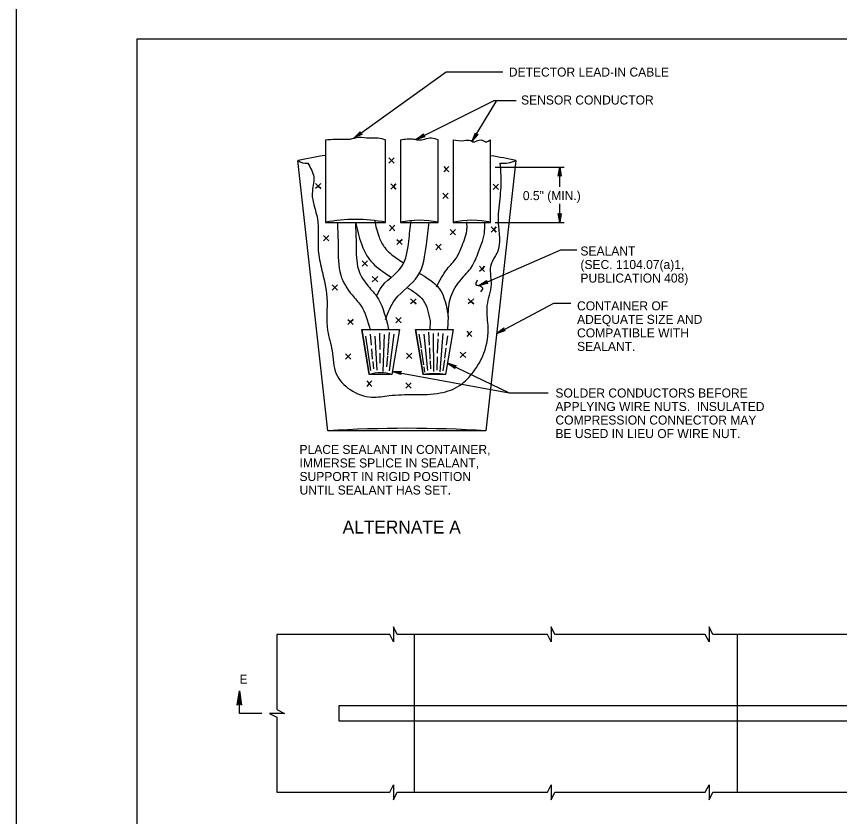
# Model space of a CAD drawing. Extents: x 2709 to 3899, y 22 to 1210.
# Drawn here: x 2708.9 to 2982.7, y 342.4 to 608.7 of the extents above; entities that cross this region are included whole.
import ezdxf

# ---------------------------------------------------------------- set-up
doc = ezdxf.new("R2010")
doc.units = 0
for name, color, linetype in [('1', 7, 'Continuous'), ('2', 7, 'Continuous'), ('3', 7, 'Continuous'), ('PLT-BNDY', 7, 'Continuous')]:
    doc.layers.add(name, color=color, linetype=linetype)

# ---------------------------------------------------------------- blocks, each defined once
blk = doc.blocks.new('RARROW')
at = {"layer": '3'}
blk.add_lwpolyline([(-2.2695, 0.285), (-2.184875, 0.12075), (0, 0), (-2.2695, 0.285), (-2.38575, 0.384625), (0, 0), (-2.183125, -0.108), (-2.262875, -0.2705), (0, 0), (-2.38575, -0.379125), (-2.262875, -0.2705)], dxfattribs=at)

msp = doc.modelspace()

# ---------------------------------------------------------------- linework, layer by layer
at = {"layer": '1'}
for q in [(3534.86, 601.17), (2748.86, 37.17)]:
    msp.add_line((2748.86, 601.17), q, dxfattribs=at)
at = {"layer": '2'}
for p, q in [((2821.13, 568.12), (2851.88, 590.22)), ((2851.88, 590.22), (2870.7, 590.22)), ((2841.88, 567.75), (2867.75, 580.75)), ((2860.5, 567.12), (2868.63, 580.75)), ((2867.75, 580.75), (2875.13, 580.75)), ((2811.63, 562.37), (2811.63, 562.37)), ((2866.63, 562.25), (2866.63, 562.25)), ((2868.13, 558.5), (2891.13, 558.5)), ((2889.63, 552), (2889.63, 558.5)), ((2889.63, 540.12), (2889.63, 546.37)), ((2828, 540.75), (2828, 540.75)), ((2858.75, 539.37), (2858.75, 540.37)), ((2868.13, 540.12), (2891.13, 540.12)), ((2862.75, 519.12), (2890, 531)), ((2890, 531), (2895.25, 531)), ((2842.63, 523.37), (2842.63, 523.37)), ((2838.75, 518.5), (2838.75, 518.5)), ((2848.63, 518.75), (2848.63, 518.75)), ((2868.63, 503.12), (2887.63, 513.25)), ((2887.63, 513.25), (2893.25, 513.25)), ((2846.5, 507.37), (2846.38, 504.5)), ((2852.5, 508.87), (2852.25, 504.5)), ((2823.75, 504.5), (2826.25, 489.5)), ((2832.25, 506.25), (2832.63, 504.5)), ((2836.25, 504.5), (2833.75, 489.5)), ((2841.63, 504.5), (2844.13, 489.5)), ((2854.13, 504.5), (2851.63, 489.5)), ((2825, 502.25), (2826.63, 490.87)), ((2826.5, 503), (2826.88, 499.25)), ((2828.13, 502.25), (2828.75, 491)), ((2829.63, 503.25), (2829.75, 497.87)), ((2831.25, 502.87), (2830.75, 490.5)), ((2832.88, 503.5), (2832.63, 500.75)), ((2834.38, 503), (2832.88, 490.75)), ((2842.75, 503), (2843.5, 498.37)), ((2844.38, 503), (2845.63, 490.87)), ((2846, 503.62), (2846.13, 499.25)), ((2847.5, 503.12), (2847.63, 490.5)), ((2849, 501.37), (2848.88, 496.62)), ((2849.13, 503.37), (2849.13, 502.25)), ((2850.75, 503.12), (2849.75, 490.37)), ((2852.25, 502.37), (2851.88, 499.25)), ((2832.63, 500.5), (2832.25, 496.12)), ((2827, 498.12), (2827.25, 494.62)), ((2829.75, 496.62), (2829.75, 493.25)), ((2832.25, 495.75), (2832, 492.12)), ((2843.5, 497.87), (2844.25, 492.75)), ((2846.25, 498.37), (2846.38, 494.62)), ((2851.75, 498.25), (2851.25, 495)), ((2827.38, 493.87), (2827.63, 491.37)), ((2846.5, 494.12), (2846.63, 491.37)), ((2848.88, 495.37), (2848.75, 491)), ((2851.25, 494.37), (2850.75, 490.75)), ((2852.25, 493.25), (2872.8, 483.37)), ((2833.93, 490.57), (2872.8, 483.37)), ((2844.38, 492.12), (2844.63, 490.25)), ((2872.8, 483.37), (2885.81, 483.37)), ((2841.15, 403.01), (2841.15, 350.51)), ((2948.65, 403.01), (2948.65, 350.51))]:
    msp.add_line(p, q, dxfattribs=at)
for points in [[(2811.63, 567.62), (2811.63, 540.12), (2831.63, 540.12), (2831.63, 567.62)], [(2836.63, 567.62), (2836.63, 540.12), (2849.13, 540.12), (2849.13, 567.62)], [(2854.13, 567.62), (2854.13, 540.12), (2866.63, 540.12), (2866.63, 567.62)], [(2832.75, 561.62), (2833.63, 560.75), (2834.5, 559.87), (2833.63, 560.75), (2834.5, 561.62), (2833.63, 560.75), (2832.75, 559.87)], [(2875, 560.75), (2865, 470.75), (2812.5, 470.75), (2802.5, 560.75)], [(2851, 558.75), (2851.88, 557.87), (2852.75, 557), (2851.88, 557.87), (2852.75, 558.75), (2851.88, 557.87), (2851, 557)], [(2808.38, 553.12), (2809.25, 552.25), (2810.13, 551.37), (2809.25, 552.25), (2810.13, 553.12), (2809.25, 552.25), (2808.38, 551.37)], [(2833.38, 553), (2834.25, 552.12), (2835.13, 551.25), (2834.25, 552.12), (2835.13, 553), (2834.25, 552.12), (2833.38, 551.25)], [(2867.5, 552.87), (2868.38, 552), (2869.25, 551.12), (2868.38, 552), (2869.25, 552.87), (2868.38, 552), (2867.5, 551.12)], [(2850.75, 549.87), (2851.63, 549), (2852.5, 548.12), (2851.63, 549), (2852.5, 549.87), (2851.63, 549), (2850.75, 548.12)], [(2833, 539.25), (2833.88, 538.37), (2834.75, 537.37), (2833.88, 538.37), (2834.75, 539.25), (2833.88, 538.37), (2833, 537.37)], [(2853.13, 537.75), (2854, 536.87), (2854.88, 536), (2854, 536.87), (2854.88, 537.75), (2854, 536.87), (2853.13, 536)], [(2866.75, 538.62), (2867.63, 537.75), (2868.5, 536.87), (2867.63, 537.75), (2868.5, 538.62), (2867.63, 537.75), (2866.75, 536.87)], [(2811, 535.75), (2811.88, 534.87), (2812.75, 534), (2811.88, 534.87), (2812.75, 535.75), (2811.88, 534.87), (2811, 534)], [(2835.38, 534.5), (2836.25, 533.62), (2837.13, 532.75), (2836.25, 533.62), (2837.13, 534.5), (2836.25, 533.62), (2835.38, 532.75)], [(2848.38, 532.87), (2849.25, 532), (2850.13, 531), (2849.25, 532), (2850.13, 532.87), (2849.25, 532), (2848.38, 531)], [(2823.88, 527.37), (2824.75, 526.5), (2825.63, 525.62), (2824.75, 526.5), (2825.63, 527.37), (2824.75, 526.5), (2823.88, 525.62)], [(2862.88, 525.62), (2863.75, 524.62), (2864.63, 523.75), (2863.75, 524.62), (2864.63, 525.62), (2863.75, 524.62), (2862.88, 523.75)], [(2827.25, 522.12), (2828.25, 521.25), (2829.13, 520.37), (2828.25, 521.25), (2829.13, 522.12), (2828.25, 521.25), (2827.25, 520.37)], [(2813.88, 519.37), (2814.75, 518.5), (2815.63, 517.62), (2814.75, 518.5), (2815.63, 519.37), (2814.75, 518.5), (2813.88, 517.62)], [(2840, 514.75), (2841, 513.87), (2841.88, 513), (2841, 513.87), (2841.88, 514.75), (2841, 513.87), (2840, 513)], [(2859.13, 514.75), (2860, 513.87), (2861, 513), (2860, 513.87), (2861, 514.75), (2860, 513.87), (2859.13, 513)], [(2819.13, 507.87), (2820, 507), (2820.88, 506.12), (2820, 507), (2820.88, 507.87), (2820, 507), (2819.13, 506.12)], [(2835.13, 508.5), (2836, 507.62), (2836.88, 506.75), (2836, 507.62), (2836.88, 508.5), (2836, 507.62), (2835.13, 506.75)], [(2833.75, 489.5), (2826.25, 489.5), (2823.75, 504.5), (2836.25, 504.5), (2833.75, 489.5)], [(2851.63, 489.5), (2844.13, 489.5), (2841.63, 504.5), (2854.13, 504.5), (2851.63, 489.5)], [(2858.65, 503.92), (2859.53, 503.04), (2860.4, 502.17), (2859.53, 503.04), (2860.4, 503.92), (2859.53, 503.04), (2858.65, 502.17)], [(2818.38, 496.37), (2819.25, 495.5), (2820.13, 494.62), (2819.25, 495.5), (2820.13, 496.37), (2819.25, 495.5), (2818.38, 494.62)], [(2838.63, 496.62), (2839.5, 495.75), (2840.38, 494.87), (2839.5, 495.75), (2840.38, 496.62), (2839.5, 495.75), (2838.63, 494.87)], [(2856.49, 496.91), (2857.36, 496.03), (2858.36, 495.16), (2857.36, 496.03), (2858.36, 496.91), (2857.36, 496.03), (2856.49, 495.16)], [(2825.38, 487.37), (2826.25, 486.5), (2827.13, 485.5), (2826.25, 486.5), (2827.13, 487.37), (2826.25, 486.5), (2825.38, 485.5)], [(2838.4, 486.72), (2839.28, 485.84), (2840.15, 484.97), (2839.28, 485.84), (2840.15, 486.72), (2839.28, 485.84), (2838.4, 484.97)], [(3030.53, 403.01), (2993.03, 403.01), (2991.78, 405.51), (2991.78, 400.51), (2990.53, 403.01), (2940.53, 403.01), (2939.28, 405.51), (2939.28, 400.51), (2938.03, 403.01), (2888.03, 403.01), (2886.78, 405.51), (2886.78, 400.51), (2885.53, 403.01), (2835.53, 403.01), (2834.28, 405.51), (2834.28, 400.51), (2833.03, 403.01), (2795.53, 403.01), (2795.53, 390.51), (2795.53, 378.01), (2798.03, 376.76), (2793.03, 376.76)], [(2782.53, 379.76), (2782.78, 379.89), (2783.03, 384.26), (2782.53, 379.76), (2782.28, 379.51), (2783.03, 384.26), (2783.28, 379.89), (2783.65, 379.76), (2783.03, 384.26), (2783.78, 379.51), (2783.65, 379.76)], [(2790.53, 376.76), (2783.03, 376.76), (2783.03, 384.26)], [(3036.15, 379.26), (2816.15, 379.26), (2816.15, 374.26), (3036.15, 374.26)], [(2793.03, 376.76), (2795.53, 375.51), (2795.53, 363.01), (2795.53, 350.51), (2833.03, 350.51), (2834.28, 353.01), (2834.28, 348.01), (2835.53, 350.51), (2885.53, 350.51), (2886.78, 353.01), (2886.78, 348.01), (2888.03, 350.51), (2938.03, 350.51), (2939.28, 353.01), (2939.28, 348.01), (2940.53, 350.51), (2990.53, 350.51)]]:
    msp.add_lwpolyline(points, dxfattribs=at)
for centre, radius, start, end in [((2838.78, 387.43), 177.08, 98.8081, 101.8126), ((2838.78, 387.43), 177.08, 78.1874, 80.9399), ((2805.08, 563.77), 3.95, 229.8258, 280.5215), ((2870.99, 568.98), 9.16, 262.7649, 296.157), ((2821.66, 488.83), 52.31, 78.9796, 101.0204), ((2842.91, 511.52), 29.33, 77.6967, 102.3033), ((2860.41, 511.83), 29.03, 77.5665, 102.4335), ((2830.03, 477.68), 12.41, 72.4052, 107.5948), ((2847.91, 467.58), 22.24, 80.2922, 99.7078), ((2838.78, 74.58), 397.04, 86.2091, 93.7909)]:
    msp.add_arc(centre, radius, start, end, dxfattribs=at)
for points in [[(2811.63, 567.62), (2815, 567.87), (2817, 567.87), (2819.88, 567.87), (2822.75, 568.5), (2826.25, 568.25), (2829.13, 568.25), (2831.63, 567.62)], [(2836.63, 567.62), (2841, 567.87), (2842.38, 567.62), (2844.75, 567.87), (2847, 568.25), (2849.13, 567.62)], [(2854.13, 567.62), (2857.75, 567.37), (2860, 567.37), (2860.63, 567), (2863.5, 567.62), (2864.88, 567), (2866.63, 567.62)], [(2805.75, 559.87), (2807.75, 555.25), (2807.25, 549.75), (2809, 541.37), (2809.25, 530.75), (2810.38, 524.62), (2812.13, 515.12), (2812.38, 504.12), (2813.88, 497.5), (2815.25, 489.75), (2819.88, 484.5), (2827.13, 482), (2832.88, 482.5), (2841, 482.87), (2849.88, 483.37), (2856.5, 486), (2860.88, 490.37), (2864.38, 496.62), (2865.75, 505.87), (2865.5, 512.5), (2866.88, 519.5), (2866.88, 526.37), (2869, 530.37), (2869.25, 540), (2869.75, 548), (2870.13, 555.75), (2869.75, 559.87)], [(2815.63, 540.12), (2815.88, 532.12), (2816.75, 522.62), (2820.5, 516), (2823.38, 512.5), (2826.5, 504.5)], [(2821.63, 540.25), (2821.88, 532.5), (2822.63, 524.5), (2825.5, 519.37), (2828.63, 515.62), (2832.25, 506.25)], [(2821.63, 540.25), (2823.63, 533), (2826.25, 527.87), (2831.5, 523.25), (2833.5, 521.87)], [(2828, 540.75), (2829.5, 535.25), (2831.38, 531.75), (2835.25, 528.25), (2837.5, 526.75)], [(2828.88, 515.87), (2829.88, 518), (2837, 525.37), (2839.38, 533.87), (2840.13, 540.75)], [(2831.63, 507.87), (2834.88, 514.5), (2842.38, 522.37), (2845.25, 532.75), (2846.13, 540.25)], [(2852.5, 508.87), (2853.38, 515.37), (2856.88, 521.25), (2860.25, 525.25), (2862.63, 530.37), (2864.63, 537.37), (2864.63, 540.25)], [(2848.63, 518.75), (2852.13, 524.62), (2855.25, 528.37), (2857.13, 532.37), (2858.75, 538.12), (2858.75, 539.37)], [(2842.63, 523.37), (2849.5, 518.12), (2852.5, 508.87)], [(2862.13, 520.87), (2861.75, 519.37), (2862.75, 519.12), (2863.88, 518.25), (2863.25, 517)], [(2838.75, 518.5), (2844.13, 514.25), (2846.5, 507.37)]]:
    msp.add_spline(points, degree=3, dxfattribs=at)
at = {"layer": 'PLT-BNDY'}
msp.add_lwpolyline([(2708.86, 616.17), (3549.86, 616.17), (3549.86, 22.17), (2708.86, 22.17)], close=True, dxfattribs=at)

# ---------------------------------------------------------------- block references
at = {"layer": '2', "xscale": 1.2574347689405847, "yscale": 1.3092961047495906}
for p, rotation in [((2821.13, 568.12), -143.8918862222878), ((2860.5, 567.12), -120.98880006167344), ((2841.88, 567.75), -152.91176770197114), ((2889.63, 558.5), 89.99999999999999), ((2889.63, 540.12), -90.00000000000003), ((2862.75, 519.12), -156.33882568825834), ((2868.63, 503.12), -151.09339468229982), ((2852.25, 493.25), 154.91533570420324), ((2833.93, 490.57), 169.7214942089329)]:
    msp.add_blockref('RARROW', p, dxfattribs=dict(at, rotation=rotation))

# ---------------------------------------------------------------- texts
at = {"layer": '2'}
for s, height, p in [('DETECTOR LEAD-IN CABLE', 3, (2872.68, 588.67)), ('SENSOR CONDUCTOR', 3, (2876.75, 579.37)), ('0.5" (MIN.)', 3, (2877.34, 547.55)), ('SEALANT', 3, (2896.5, 529.12)), ('(SEC. 1104.07(a)1,', 3, (2896.5, 524.62)), ('PUBLICATION 408)', 3, (2896.5, 520.12)), ('CONTAINER OF', 3, (2895.38, 510.87)), ('ADEQUATE SIZE AND', 3, (2895.38, 506.37)), ('COMPATIBLE WITH', 3, (2895.38, 501.87)), ('SEALANT.', 3, (2895.38, 497.37)), ('SOLDER CONDUCTORS BEFORE', 3, (2888.18, 481.87)), ('APPLYING WIRE NUTS.  INSULATED', 3, (2888.18, 477.37)), ('COMPRESSION CONNECTOR MAY', 3, (2888.18, 472.87)), ('BE USED IN LIEU OF WIRE NUT.', 3, (2888.18, 468.37)), ('PLACE SEALANT IN CONTAINER,', 3, (2803.03, 463.08)), ('IMMERSE SPLICE IN SEALANT,', 3, (2803.03, 458.58)), ('SUPPORT IN RIGID POSITION', 3, (2803.03, 454.08)), ('UNTIL SEALANT HAS SET.', 3, (2803.03, 449.58)), ('ALTERNATE A', 4.3, (2817.38, 436.6)), ('E', 3, (2783.07, 386.64))]:
    msp.add_text(s, height=height, dxfattribs=at).set_placement(p)

doc.saveas('drawing.dxf')
